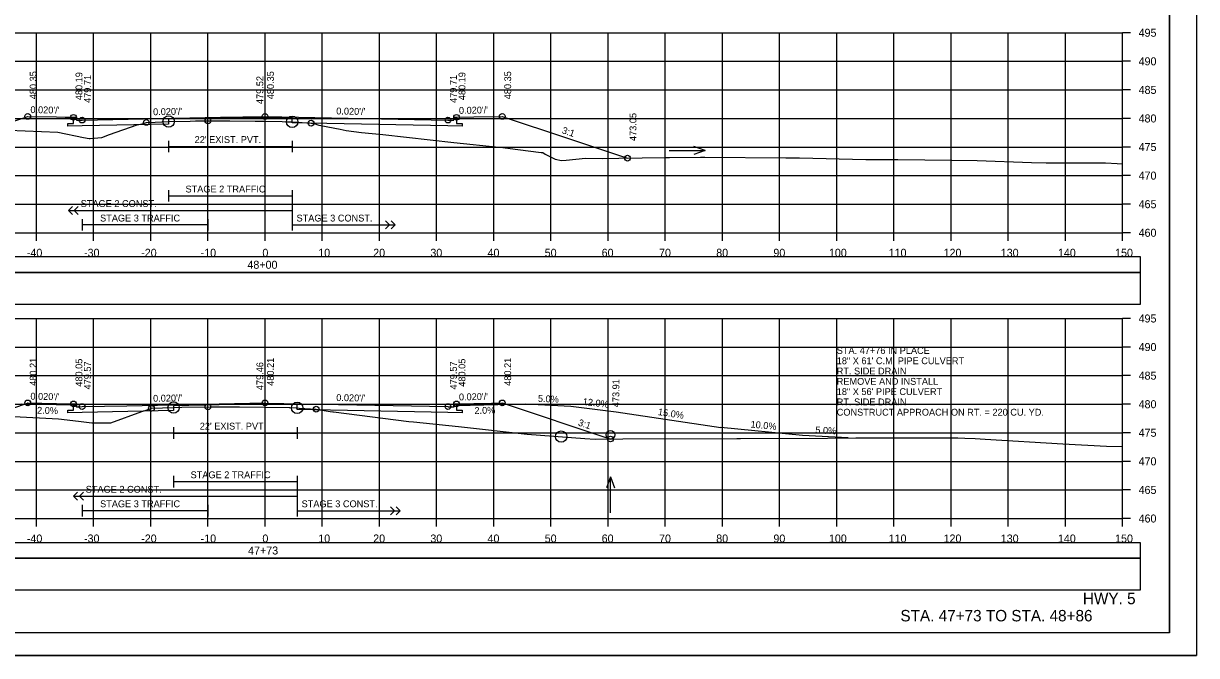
# Model space of a CAD drawing. Extents: x 1371057 to 1372761, y 380005 to 390517.
# Drawn here: x 1371518.6 to 1371723.8, y 382778.5 to 382889.1 of the extents above; entities that cross this region are included whole.
import ezdxf

# ---------------------------------------------------------------- set-up
doc = ezdxf.new("R2010")
doc.units = 0
for name, color, linetype in [('R_Alt Surface', 7, 'Continuous'), ('R_Axis', 7, 'Continuous'), ('R_Axis Annot', 7, 'Continuous'), ('R_Border', 7, 'Continuous'), ('R_Detour', 7, 'Continuous'), ('R_Dimension', 7, 'Continuous'), ('R_Draft', 7, 'Continuous'), ('R_Drive', 7, 'Continuous'), ('R_Exist Surface', 7, 'Continuous'), ('R_Fin Surface', 7, 'Continuous'), ('R_Grid', 7, 'Continuous'), ('R_No Plot', 7, 'Continuous'), ('R_Striping', 7, 'Continuous'), ('R_Water', 7, 'Continuous'), ('R_Water Annot', 7, 'Continuous'), ('R_Xsect Elev', 7, 'Continuous'), ('R_Xsect Slope', 7, 'Continuous')]:
    doc.layers.add(name, color=color, linetype=linetype)

msp = doc.modelspace()

# ---------------------------------------------------------------- linework, layer by layer
at = {"layer": 'R_Alt Surface'}
for points in [[(1371594.37, 382872.65), (1371594.37, 382871.57), (1371595.37, 382871.55), (1371595.37, 382871.12), (1371592.87, 382871.17), (1371565.61, 382871.71), (1371565.61, 382872.54), (1371560.87, 382872.64), (1371544.01, 382872.3), (1371544.01, 382871.47), (1371528.87, 382871.17), (1371526.37, 382871.12), (1371526.37, 382871.55), (1371527.37, 382871.57), (1371527.37, 382872.65)], [(1371594.37, 382872.65), (1371594.37, 382871.57), (1371595.37, 382871.55), (1371595.37, 382871.12), (1371592.87, 382871.17), (1371565.61, 382871.71), (1371565.61, 382872.54), (1371560.87, 382872.64), (1371544.01, 382872.3), (1371544.01, 382871.47), (1371528.87, 382871.17), (1371526.37, 382871.12), (1371526.37, 382871.55), (1371527.37, 382871.57), (1371527.37, 382872.65)], [(1371544.01, 382868.56), (1371544.01, 382866.56)], [(1371544.01, 382867.56), (1371565.61, 382867.56)], [(1371565.61, 382868.56), (1371565.61, 382866.56)], [(1371594.37, 382822.51), (1371594.37, 382821.42), (1371595.37, 382821.4), (1371595.37, 382820.97), (1371592.87, 382821.02), (1371566.5, 382821.55), (1371566.5, 382822.38), (1371560.87, 382822.5), (1371544.88, 382822.18), (1371544.88, 382821.35), (1371528.87, 382821.02), (1371526.37, 382820.97), (1371526.37, 382821.4), (1371527.37, 382821.42), (1371527.37, 382822.51)], [(1371594.37, 382822.51), (1371594.37, 382821.42), (1371595.37, 382821.4), (1371595.37, 382820.97), (1371592.87, 382821.02), (1371566.5, 382821.55), (1371566.5, 382822.38), (1371560.87, 382822.5), (1371544.88, 382822.18), (1371544.88, 382821.35), (1371528.87, 382821.02), (1371526.37, 382820.97), (1371526.37, 382821.4), (1371527.37, 382821.42), (1371527.37, 382822.51)], [(1371544.88, 382818.41), (1371544.88, 382816.41)], [(1371566.5, 382818.41), (1371566.5, 382816.41)], [(1371544.88, 382817.41), (1371566.5, 382817.41)]]:
    msp.add_lwpolyline(points, dxfattribs=at)
at = {"layer": 'R_Axis'}
for p, q in [((1371710.87, 382852.45), (1371710.87, 382887.45)), ((1371712.27, 382887.45), (1371710.87, 382887.45)), ((1371712.27, 382882.45), (1371710.87, 382882.45)), ((1371712.27, 382877.45), (1371710.87, 382877.45)), ((1371712.27, 382872.45), (1371710.87, 382872.45)), ((1371712.27, 382867.45), (1371710.87, 382867.45)), ((1371712.27, 382862.45), (1371710.87, 382862.45)), ((1371712.27, 382857.45), (1371710.87, 382857.45)), ((1371410.87, 382852.45), (1371710.87, 382852.45)), ((1371520.87, 382851.05), (1371520.87, 382852.45)), ((1371530.87, 382851.05), (1371530.87, 382852.45)), ((1371540.87, 382851.05), (1371540.87, 382852.45)), ((1371550.87, 382851.05), (1371550.87, 382852.45)), ((1371560.87, 382851.05), (1371560.87, 382852.45)), ((1371570.87, 382851.05), (1371570.87, 382852.45)), ((1371580.87, 382851.05), (1371580.87, 382852.45)), ((1371590.87, 382851.05), (1371590.87, 382852.45)), ((1371600.87, 382851.05), (1371600.87, 382852.45)), ((1371610.87, 382851.05), (1371610.87, 382852.45)), ((1371620.87, 382851.05), (1371620.87, 382852.45)), ((1371630.87, 382851.05), (1371630.87, 382852.45)), ((1371640.87, 382851.05), (1371640.87, 382852.45)), ((1371650.87, 382851.05), (1371650.87, 382852.45)), ((1371660.87, 382851.05), (1371660.87, 382852.45)), ((1371670.87, 382851.05), (1371670.87, 382852.45)), ((1371680.87, 382851.05), (1371680.87, 382852.45)), ((1371690.87, 382851.05), (1371690.87, 382852.45)), ((1371700.87, 382851.05), (1371700.87, 382852.45)), ((1371710.87, 382851.05), (1371710.87, 382852.45)), ((1371712.27, 382852.45), (1371710.87, 382852.45)), ((1371710.87, 382802.45), (1371710.87, 382837.45)), ((1371712.27, 382837.45), (1371710.87, 382837.45)), ((1371712.27, 382832.45), (1371710.87, 382832.45)), ((1371712.27, 382827.45), (1371710.87, 382827.45)), ((1371712.27, 382822.45), (1371710.87, 382822.45)), ((1371712.27, 382817.45), (1371710.87, 382817.45)), ((1371712.27, 382812.45), (1371710.87, 382812.45)), ((1371712.27, 382807.45), (1371710.87, 382807.45)), ((1371410.87, 382802.45), (1371710.87, 382802.45)), ((1371520.87, 382801.05), (1371520.87, 382802.45)), ((1371530.87, 382801.05), (1371530.87, 382802.45)), ((1371540.87, 382801.05), (1371540.87, 382802.45)), ((1371550.87, 382801.05), (1371550.87, 382802.45)), ((1371560.87, 382801.05), (1371560.87, 382802.45)), ((1371570.87, 382801.05), (1371570.87, 382802.45)), ((1371580.87, 382801.05), (1371580.87, 382802.45)), ((1371590.87, 382801.05), (1371590.87, 382802.45)), ((1371600.87, 382801.05), (1371600.87, 382802.45)), ((1371610.87, 382801.05), (1371610.87, 382802.45)), ((1371620.87, 382801.05), (1371620.87, 382802.45)), ((1371630.87, 382801.05), (1371630.87, 382802.45)), ((1371640.87, 382801.05), (1371640.87, 382802.45)), ((1371650.87, 382801.05), (1371650.87, 382802.45)), ((1371660.87, 382801.05), (1371660.87, 382802.45)), ((1371670.87, 382801.05), (1371670.87, 382802.45)), ((1371680.87, 382801.05), (1371680.87, 382802.45)), ((1371690.87, 382801.05), (1371690.87, 382802.45)), ((1371700.87, 382801.05), (1371700.87, 382802.45)), ((1371710.87, 382801.05), (1371710.87, 382802.45)), ((1371712.27, 382802.45), (1371710.87, 382802.45))]:
    msp.add_line(p, q, dxfattribs=at)
at = {"layer": 'R_Border'}
for q in [(1371719.05, 382987.91), (1371402.87, 382782.45)]:
    msp.add_line((1371719.05, 382782.45), q, dxfattribs=at)
at = {"layer": 'R_Detour'}
for points in [[(1371407.72, 382845.5), (1371714.03, 382845.5), (1371714.03, 382848.21), (1371407.72, 382848.21)], [(1371407.72, 382795.5), (1371714.03, 382795.5), (1371714.03, 382798.21), (1371407.72, 382798.21)]]:
    msp.add_lwpolyline(points, close=True, dxfattribs=at)
at = {"layer": 'R_Dimension'}
for points in [[(1371407.72, 382839.98), (1371714.03, 382839.98), (1371714.03, 382845.5), (1371407.72, 382845.5)], [(1371407.72, 382789.98), (1371714.03, 382789.98), (1371714.03, 382795.5), (1371407.72, 382795.5)]]:
    msp.add_lwpolyline(points, close=True, dxfattribs=at)
at = {"layer": 'R_Drive'}
for p, q in [((1371527.38, 382822.26), (1371518.36, 382822.44)), ((1371527.88, 382822.01), (1371527.38, 382822.26)), ((1371593.87, 382822), (1371594.37, 382822.25)), ((1371594.37, 382822.25), (1371606.37, 382822.49)), ((1371606.37, 382822.49), (1371614.36, 382822.1)), ((1371614.36, 382822.1), (1371622.3, 382821.14)), ((1371622.3, 382821.14), (1371640.61, 382818.4)), ((1371654.88, 382816.97), (1371640.61, 382818.4)), ((1371662.87, 382816.57), (1371654.88, 382816.97))]:
    msp.add_line(p, q, dxfattribs=at)
at = {"layer": 'R_Exist Surface'}
for points in [[(1371516.05, 382870.4), (1371524.64, 382870.08), (1371529.12, 382869.13), (1371530.13, 382868.92), (1371530.3, 382868.93), (1371532.31, 382869.13), (1371533.65, 382869.63), (1371538.5, 382871.35), (1371539.39, 382871.54), (1371540.11, 382871.75), (1371541.63, 382871.82), (1371544.01, 382871.91), (1371547.76, 382871.99), (1371548.73, 382872.01), (1371549.85, 382872.02), (1371554.09, 382872.05), (1371554.27, 382872.05), (1371554.74, 382872.04), (1371559.17, 382871.99), (1371560.69, 382871.97), (1371563.85, 382871.91), (1371564.75, 382871.89), (1371564.96, 382871.88), (1371565.61, 382871.85), (1371566.58, 382871.78), (1371568.93, 382871.63), (1371569.44, 382871.56), (1371570.28, 382871.3), (1371570.61, 382871.21), (1371573.99, 382870.55), (1371575.09, 382870.36), (1371577.75, 382870.02), (1371581.49, 382869.63), (1371581.49, 382869.63), (1371593.89, 382868.23), (1371601.77, 382867.45), (1371602.02, 382867.43), (1371605.1, 382867.03), (1371609.15, 382866.52), (1371609.45, 382866.48), (1371609.87, 382866.23), (1371611.6, 382865.35), (1371612.75, 382865.1), (1371613.56, 382865.13), (1371616.9, 382865.52), (1371619.86, 382865.44), (1371622.77, 382865.48), (1371630.89, 382865.61), (1371630.9, 382865.62), (1371631.62, 382865.61), (1371637.02, 382865.68), (1371637.75, 382865.68), (1371637.75, 382865.69), (1371637.82, 382865.69), (1371651.96, 382865.58), (1371654.35, 382865.57), (1371665.96, 382865.29), (1371671.57, 382865.26), (1371681.01, 382865.16), (1371685.46, 382865.12), (1371694.93, 382864.74), (1371697.51, 382864.71), (1371706.77, 382864.69), (1371707.76, 382864.66), (1371707.9, 382864.66), (1371709.93, 382864.58), (1371710.87, 382864.54)], [(1371516.92, 382820.31), (1371524.77, 382819.87), (1371528.26, 382819.5), (1371530.56, 382819.21), (1371533.26, 382819.2), (1371533.91, 382819.22), (1371539.34, 382821.15), (1371539.91, 382821.35), (1371540.06, 382821.4), (1371540.99, 382821.73), (1371544.87, 382821.86), (1371544.88, 382821.86), (1371546.3, 382821.91), (1371546.33, 382821.91), (1371551.46, 382821.99), (1371551.55, 382821.99), (1371555.65, 382821.99), (1371555.7, 382821.99), (1371555.72, 382821.99), (1371556.11, 382821.99), (1371556.38, 382821.98), (1371565.11, 382821.85), (1371565.18, 382821.85), (1371566.32, 382821.81), (1371566.33, 382821.81), (1371566.5, 382821.8), (1371566.84, 382821.77), (1371569.82, 382821.58), (1371571.94, 382821.22), (1371572.24, 382821.17), (1371572.73, 382821.11), (1371572.84, 382821.09), (1371586.01, 382819.45), (1371586.83, 382819.37), (1371594.74, 382818.53), (1371606.75, 382817.23), (1371616.83, 382816.45), (1371618.63, 382816.31), (1371623.48, 382816.39), (1371643.4, 382816.45), (1371644.01, 382816.45), (1371659.27, 382816.5), (1371664.19, 382816.59), (1371680.28, 382816.56), (1371682.04, 382816.55), (1371683.3, 382816.51), (1371685.09, 382816.44), (1371686.86, 382816.32), (1371700.42, 382815.5), (1371708.03, 382815.12), (1371710.87, 382815.06)]]:
    msp.add_lwpolyline(points, dxfattribs=at)
at = {"layer": 'R_Fin Surface'}
for points in [[(1371507.02, 382868.69), (1371519.37, 382872.8), (1371519.37, 382872.81), (1371524.37, 382872.71), (1371525.9, 382872.67), (1371527.37, 382872.65), (1371527.63, 382872.65), (1371527.87, 382872.65), (1371527.87, 382872.45), (1371527.88, 382872.15), (1371528.32, 382872.15), (1371528.87, 382872.17), (1371553.08, 382872.65), (1371560.87, 382872.81), (1371560.87, 382872.81), (1371592.87, 382872.17), (1371592.87, 382872.17), (1371593.87, 382872.15), (1371593.87, 382872.65), (1371594.37, 382872.65), (1371597.37, 382872.71), (1371602.37, 382872.81), (1371613.75, 382869.01), (1371624.28, 382865.5)], [(1371514.11, 382820.91), (1371519.34, 382822.65), (1371519.37, 382822.67), (1371524.36, 382822.57), (1371524.37, 382822.57), (1371527.37, 382822.51), (1371527.37, 382822.51), (1371527.67, 382822.51), (1371527.87, 382822.51), (1371527.87, 382822.33), (1371527.88, 382822.01), (1371527.88, 382822.01), (1371528.47, 382822.02), (1371528.87, 382822.03), (1371536.71, 382822.18), (1371560.87, 382822.67), (1371560.98, 382822.66), (1371592.87, 382822.03), (1371592.88, 382822.02), (1371593.87, 382822.01), (1371593.87, 382822.51), (1371594.16, 382822.51), (1371594.37, 382822.51), (1371597.37, 382822.57), (1371600.51, 382822.63), (1371602.35, 382822.66), (1371602.37, 382822.67), (1371621.18, 382816.39), (1371621.29, 382816.36)]]:
    msp.add_lwpolyline(points, dxfattribs=at)
at = {"layer": 'R_Grid'}
for p, q in [((1371410.87, 382887.45), (1371710.87, 382887.45)), ((1371520.87, 382852.45), (1371520.87, 382887.45)), ((1371530.87, 382852.45), (1371530.87, 382887.45)), ((1371540.87, 382852.45), (1371540.87, 382887.45)), ((1371550.87, 382852.45), (1371550.87, 382887.45)), ((1371560.87, 382852.45), (1371560.87, 382887.45)), ((1371570.87, 382852.45), (1371570.87, 382887.45)), ((1371580.87, 382852.45), (1371580.87, 382887.45)), ((1371590.87, 382852.45), (1371590.87, 382887.45)), ((1371600.87, 382852.45), (1371600.87, 382887.45)), ((1371610.87, 382852.45), (1371610.87, 382887.45)), ((1371620.87, 382852.45), (1371620.87, 382887.45)), ((1371630.87, 382852.45), (1371630.87, 382887.45)), ((1371640.87, 382852.45), (1371640.87, 382887.45)), ((1371650.87, 382852.45), (1371650.87, 382887.45)), ((1371660.87, 382852.45), (1371660.87, 382887.45)), ((1371670.87, 382852.45), (1371670.87, 382887.45)), ((1371680.87, 382852.45), (1371680.87, 382887.45)), ((1371690.87, 382852.45), (1371690.87, 382887.45)), ((1371700.87, 382852.45), (1371700.87, 382887.45)), ((1371710.87, 382852.45), (1371710.87, 382887.45)), ((1371410.87, 382882.45), (1371710.87, 382882.45)), ((1371410.87, 382877.45), (1371710.87, 382877.45)), ((1371410.87, 382872.45), (1371710.87, 382872.45)), ((1371410.87, 382867.45), (1371710.87, 382867.45)), ((1371410.87, 382862.45), (1371710.87, 382862.45)), ((1371410.87, 382857.45), (1371710.87, 382857.45)), ((1371410.87, 382852.45), (1371710.87, 382852.45)), ((1371410.87, 382837.45), (1371710.87, 382837.45)), ((1371520.87, 382802.45), (1371520.87, 382837.45)), ((1371530.87, 382802.45), (1371530.87, 382837.45)), ((1371540.87, 382802.45), (1371540.87, 382837.45)), ((1371550.87, 382802.45), (1371550.87, 382837.45)), ((1371560.87, 382802.45), (1371560.87, 382837.45)), ((1371570.87, 382802.45), (1371570.87, 382837.45)), ((1371580.87, 382802.45), (1371580.87, 382837.45)), ((1371590.87, 382802.45), (1371590.87, 382837.45)), ((1371600.87, 382802.45), (1371600.87, 382837.45)), ((1371610.87, 382802.45), (1371610.87, 382837.45)), ((1371620.87, 382802.45), (1371620.87, 382837.45)), ((1371630.87, 382802.45), (1371630.87, 382837.45)), ((1371640.87, 382802.45), (1371640.87, 382837.45)), ((1371650.87, 382802.45), (1371650.87, 382837.45)), ((1371660.87, 382802.45), (1371660.87, 382837.45)), ((1371670.87, 382802.45), (1371670.87, 382837.45)), ((1371680.87, 382802.45), (1371680.87, 382837.45)), ((1371690.87, 382802.45), (1371690.87, 382837.45)), ((1371700.87, 382802.45), (1371700.87, 382837.45)), ((1371710.87, 382802.45), (1371710.87, 382837.45)), ((1371410.87, 382832.45), (1371710.87, 382832.45)), ((1371410.87, 382827.45), (1371710.87, 382827.45)), ((1371410.87, 382822.45), (1371710.87, 382822.45)), ((1371410.87, 382817.45), (1371710.87, 382817.45)), ((1371410.87, 382812.45), (1371710.87, 382812.45)), ((1371410.87, 382807.45), (1371710.87, 382807.45)), ((1371410.87, 382802.45), (1371710.87, 382802.45))]:
    msp.add_line(p, q, dxfattribs=at)
at = {"layer": 'R_No Plot'}
msp.add_line((1371390.47, 382778.47), (1371723.8, 382778.47), dxfattribs=at)
for points in [[(1371390.46, 382991.81), (1371723.8, 382991.81), (1371723.8, 382778.47), (1371390.46, 382778.47)], [(1371636.79, 382987.91), (1371656.41, 382987.91), (1371656.41, 382978.03), (1371672.52, 382978.03), (1371695.72, 382978.03), (1371695.84, 382949.88), (1371719.05, 382949.88), (1371719.05, 382782.45), (1371402.87, 382782.45), (1371402.87, 382987.91)]]:
    msp.add_lwpolyline(points, close=True, dxfattribs=at)
for centre, radius in [((1371519.37, 382872.81), 0.5), ((1371527.37, 382872.65), 0.5), ((1371560.87, 382872.81), 0.5), ((1371594.37, 382872.65), 0.5), ((1371602.37, 382872.81), 0.5), ((1371528.87, 382872.17), 0.5), ((1371540.11, 382871.75), 0.5), ((1371544.01, 382871.91), 1), ((1371550.88, 382872.03), 0.5), ((1371565.61, 382871.85), 1), ((1371568.93, 382871.63), 0.5), ((1371592.87, 382872.17), 0.5), ((1371624.28, 382865.5), 0.5), ((1371519.37, 382822.67), 0.5), ((1371527.37, 382822.51), 0.5), ((1371528.87, 382822.03), 0.5), ((1371540.99, 382821.73), 0.5), ((1371544.88, 382821.86), 1), ((1371550.88, 382821.98), 0.5), ((1371560.87, 382822.67), 0.5), ((1371566.5, 382821.8), 1), ((1371569.82, 382821.58), 0.5), ((1371592.87, 382822.03), 0.5), ((1371594.37, 382822.51), 0.5), ((1371602.37, 382822.67), 0.5), ((1371621.29, 382816.36), 0.5)]:
    msp.add_circle(centre, radius, dxfattribs=at)
at = {"layer": 'R_Striping'}
for p, q in [((1371543.99, 382859.9), (1371543.99, 382857.9)), ((1371543.99, 382858.9), (1371565.62, 382858.9)), ((1371565.62, 382859.9), (1371565.62, 382852.82)), ((1371526.5, 382856.36), (1371527.21, 382857.07)), ((1371527.5, 382856.36), (1371528.21, 382857.07)), ((1371526.5, 382856.36), (1371565.62, 382856.36)), ((1371527.21, 382855.65), (1371526.5, 382856.36)), ((1371528.21, 382855.65), (1371527.5, 382856.36)), ((1371528.87, 382854.82), (1371528.87, 382852.82)), ((1371550.87, 382854.82), (1371550.87, 382852.82)), ((1371550.87, 382853.82), (1371528.87, 382853.82)), ((1371565.62, 382853.82), (1371583.62, 382853.82)), ((1371565.66, 382853.82), (1371575.66, 382853.82)), ((1371582.62, 382853.82), (1371581.92, 382854.52)), ((1371581.92, 382853.11), (1371582.62, 382853.82)), ((1371583.62, 382853.82), (1371582.92, 382854.52)), ((1371582.92, 382853.11), (1371583.62, 382853.82)), ((1371544.88, 382809.9), (1371544.88, 382807.9)), ((1371566.51, 382809.9), (1371566.51, 382802.82)), ((1371544.88, 382808.9), (1371566.51, 382808.9)), ((1371527.39, 382806.36), (1371528.09, 382807.07)), ((1371527.39, 382806.36), (1371566.51, 382806.36)), ((1371528.09, 382805.65), (1371527.39, 382806.36)), ((1371528.39, 382806.36), (1371529.09, 382807.07)), ((1371529.09, 382805.65), (1371528.39, 382806.36)), ((1371528.87, 382804.82), (1371528.87, 382802.82)), ((1371550.87, 382803.82), (1371528.87, 382803.82)), ((1371550.87, 382804.82), (1371550.87, 382802.82)), ((1371566.51, 382803.82), (1371584.51, 382803.82)), ((1371566.54, 382803.82), (1371576.54, 382803.82)), ((1371583.51, 382803.82), (1371582.8, 382804.52)), ((1371582.8, 382803.11), (1371583.51, 382803.82)), ((1371584.51, 382803.82), (1371583.8, 382804.52)), ((1371583.8, 382803.11), (1371584.51, 382803.82))]:
    msp.add_line(p, q, dxfattribs=at)
at = {"layer": 'R_Water'}
for centre, radius in [((1371612.66, 382816.78), 1), ((1371621.29, 382817.11), 0.75)]:
    msp.add_circle(centre, radius, dxfattribs=at)
at = {"layer": 'R_Water Annot'}
for p, q in [((1371637.83, 382866.84), (1371635.9, 382867.54)), ((1371631.54, 382866.84), (1371637.83, 382866.84)), ((1371637.83, 382866.84), (1371635.9, 382866.14)), ((1371621.29, 382809.74), (1371620.59, 382807.81)), ((1371621.29, 382803.45), (1371621.29, 382809.74)), ((1371621.29, 382809.74), (1371621.99, 382807.81))]:
    msp.add_line(p, q, dxfattribs=at)
at = {"layer": 'R_Xsect Elev'}
for p, q in [((1371560.87, 382871.97), (1371560.87, 382881.97)), ((1371560.87, 382821.91), (1371560.87, 382831.91))]:
    msp.add_line(p, q, dxfattribs=at)

# ---------------------------------------------------------------- texts
at = {"layer": 'R_Axis Annot'}
for s, p in [('495', (1371713.67, 382886.75)), ('490', (1371713.67, 382881.75)), ('485', (1371713.67, 382876.75)), ('480', (1371713.67, 382871.75)), ('475', (1371713.67, 382866.75)), ('470', (1371713.67, 382861.75)), ('465', (1371713.67, 382856.75)), ('460', (1371713.67, 382851.75)), ('-40', (1371519.21, 382848.25)), ('-30', (1371529.21, 382848.25)), ('-20', (1371539.21, 382848.25)), ('-10', (1371549.61, 382848.25)), ('0', (1371560.41, 382848.25)), ('10', (1371570.18, 382848.25)), ('20', (1371579.79, 382848.25)), ('30', (1371589.79, 382848.25)), ('40', (1371599.79, 382848.25)), ('50', (1371609.79, 382848.25)), ('60', (1371619.75, 382848.25)), ('70', (1371629.79, 382848.25)), ('80', (1371639.79, 382848.25)), ('90', (1371649.79, 382848.25)), ('100', (1371659.5, 382848.25)), ('110', (1371669.95, 382848.25)), ('120', (1371679.56, 382848.25)), ('130', (1371689.56, 382848.25)), ('140', (1371699.56, 382848.25)), ('150', (1371709.56, 382848.25)), ('48+00', (1371557.79, 382846.15)), ('495', (1371713.67, 382836.75)), ('490', (1371713.67, 382831.75)), ('485', (1371713.67, 382826.75)), ('480', (1371713.67, 382821.75)), ('475', (1371713.67, 382816.75)), ('470', (1371713.67, 382811.75)), ('465', (1371713.67, 382806.75)), ('460', (1371713.67, 382801.75)), ('-40', (1371519.21, 382798.25)), ('-30', (1371529.21, 382798.25)), ('-20', (1371539.21, 382798.25)), ('-10', (1371549.61, 382798.25)), ('0', (1371560.41, 382798.25)), ('10', (1371570.18, 382798.25)), ('20', (1371579.79, 382798.25)), ('30', (1371589.79, 382798.25)), ('40', (1371599.79, 382798.25)), ('50', (1371609.79, 382798.25)), ('60', (1371619.75, 382798.25)), ('70', (1371629.79, 382798.25)), ('80', (1371639.79, 382798.25)), ('90', (1371649.79, 382798.25)), ('100', (1371659.5, 382798.25)), ('110', (1371669.95, 382798.25)), ('120', (1371679.56, 382798.25)), ('130', (1371689.56, 382798.25)), ('140', (1371699.56, 382798.25)), ('150', (1371709.56, 382798.25)), ('47+73', (1371557.91, 382796.15))]:
    msp.add_text(s, height=1.4, dxfattribs=at).set_placement(p)
at = {"layer": 'R_Draft'}
for s, p in [('HWY. 5', (1371703.93, 382787.45)), ('STA. 47+73 TO STA. 48+86', (1371672.01, 382784.45))]:
    msp.add_text(s, height=2, dxfattribs=at).set_placement(p)
at = {"layer": 'R_Striping'}
for s, p in [('STAGE 2 TRAFFIC', (1371546.96, 382859.5)), ('STAGE 2 CONST.', (1371528.63, 382856.96)), ('STAGE 3 TRAFFIC', (1371532.02, 382854.42)), ('STAGE 3 CONST.', (1371566.38, 382854.42)), ('STAGE 2 TRAFFIC', (1371547.85, 382809.5)), ('STAGE 2 CONST.', (1371529.51, 382806.96)), ('STAGE 3 TRAFFIC', (1371532.02, 382804.42)), ('STAGE 3 CONST.', (1371567.27, 382804.42))]:
    msp.add_text(s, height=1.2, dxfattribs=at).set_placement(p)
at = {"layer": 'R_Water'}
for p in [(1371548.56, 382868.16), (1371549.45, 382818.01)]:
    msp.add_text("22' EXIST. PVT.", height=1.2, dxfattribs=at).set_placement(p)
at = {"layer": 'R_Water Annot'}
for s, p in [('STA. 47+76 IN PLACE', (1371660.87, 382831.25)), ('18" X 61\' C.M. PIPE CULVERT', (1371660.87, 382829.45)), ('RT. SIDE DRAIN', (1371660.87, 382827.65)), ('REMOVE AND INSTALL', (1371660.87, 382825.85)), ('18" X 56\' PIPE CULVERT', (1371660.87, 382824.05)), ('RT. SIDE DRAIN', (1371660.87, 382822.25)), ('CONSTRUCT APPROACH ON RT. = 220 CU. YD.', (1371660.87, 382820.45))]:
    msp.add_text(s, height=1.2, dxfattribs=at).set_placement(p)
at = {"layer": 'R_Xsect Elev'}
for s, rotation, p in [('480.35', 90, (1371520.92, 382875.81)), ('480.19', 90, (1371528.92, 382875.65)), ('479.71', 90, (1371530.42, 382875.17)), ('479.52', 90, (1371560.57, 382874.97)), ('480.35', 90, (1371562.42, 382875.81)), ('479.71', 90, (1371594.42, 382875.17)), ('480.19', 90, (1371595.92, 382875.65)), ('480.35', 90, (1371603.92, 382875.81)), ('473.05', 90, (1371625.83, 382868.5)), ('480.21', 90, (1371520.92, 382825.67)), ('480.05', 90, (1371528.92, 382825.51)), ('480.21', 90, (1371562.42, 382825.67)), ('480.05', 90, (1371595.92, 382825.51)), ('480.21', 90, (1371603.92, 382825.67)), ('479.57', 90, (1371530.42, 382825.03)), ('479.46', 90, (1371560.57, 382824.91)), ('479.57', 90, (1371594.42, 382825.03)), ('473.91', 90, (1371622.84, 382821.92)), ('5.0%', 357.1376, (1371608.58, 382822.88)), ('2.0%', 358.8542, (1371520.99, 382820.79)), ('2.0%', 1.1458, (1371597.51, 382820.74)), ('12.0%', 353.1572, (1371616.39, 382822.35)), ('15.0%', 351.4692, (1371629.54, 382820.56)), ('10.0%', 354.2894, (1371645.75, 382818.38)), ('5.0%', 357.1376, (1371657.1, 382817.36))]:
    msp.add_text(s, height=1.2, rotation=rotation, dxfattribs=at).set_placement(p)
at = {"layer": 'R_Xsect Slope'}
for s, rotation, p in [("0.020'/'", 358.8542, (1371519.82, 382873.4)), ("0.020'/'", 1.1458, (1371541.3, 382873.01)), ("0.020'/'", 358.8542, (1371573.32, 382873.16)), ("0.020'/'", 1.1458, (1371594.8, 382873.25)), ('3:1', 341.5655, (1371612.7, 382869.89)), ("0.020'/'", 358.8542, (1371519.82, 382823.26)), ("0.020'/'", 1.1458, (1371541.3, 382822.87)), ("0.020'/'", 358.8542, (1371573.32, 382823.02)), ("0.020'/'", 1.1457, (1371594.8, 382823.11)), ('3:1', 341.5649, (1371615.53, 382818.75))]:
    msp.add_text(s, height=1.2, rotation=rotation, dxfattribs=at).set_placement(p)

doc.saveas('drawing.dxf')
